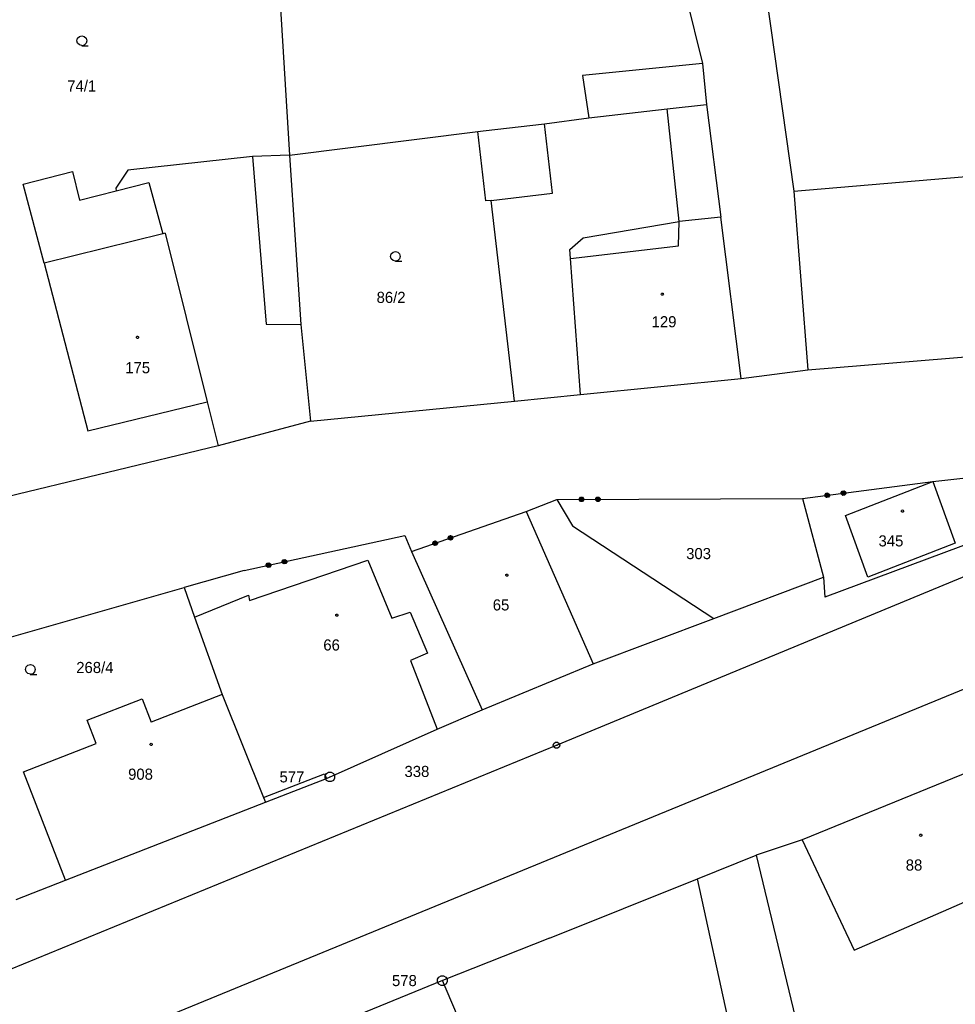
# Model space of a CAD drawing. Extents: x -757994 to -755874, y -1047691 to -1046119.
# Drawn here: x -757332.6 to -757261.1, y -1047147.5 to -1047072.3 of the extents above; entities that cross this region are included whole.
import ezdxf

# ---------------------------------------------------------------- set-up
doc = ezdxf.new("R2010")
doc.units = 0
doc.layers.add('katastrální mapa', color=7, linetype='Continuous')

msp = doc.modelspace()

# ---------------------------------------------------------------- linework, layer by layer
at = {"layer": 'katastrální mapa'}
for p, q in [((-757313.6, -1047056.48), (-757311.96, -1047082.63)), ((-757284.87, -1047057.51), (-757280.42, -1047075.65)), ((-757276.65, -1047062.56), (-757273.46, -1047085.38)), ((-757280.42, -1047075.65), (-757289.58, -1047076.55)), ((-757280.42, -1047075.65), (-757280.12, -1047078.76)), ((-757289.58, -1047076.55), (-757289.1, -1047079.79)), ((-757289.1, -1047079.79), (-757283.13, -1047079.1)), ((-757283.13, -1047079.1), (-757280.12, -1047078.76)), ((-757282.2, -1047087.71), (-757283.13, -1047079.1)), ((-757280.12, -1047078.76), (-757279.03, -1047087.37)), ((-757292.49, -1047080.24), (-757289.1, -1047079.79)), ((-757297.58, -1047080.84), (-757297.18, -1047080.79)), ((-757297.18, -1047080.79), (-757292.49, -1047080.24)), ((-757291.87, -1047085.55), (-757292.49, -1047080.24)), ((-757311.96, -1047082.63), (-757297.58, -1047080.84)), ((-757296.96, -1047086.14), (-757297.58, -1047080.84)), ((-757314.78, -1047082.75), (-757324.32, -1047083.79)), ((-757311.96, -1047082.63), (-757314.78, -1047082.75)), ((-757314.78, -1047082.75), (-757313.74, -1047095.54)), ((-757311.96, -1047082.63), (-757311.09, -1047095.57)), ((-757324.32, -1047083.79), (-757325.22, -1047085.16)), ((-757332.3, -1047084.86), (-757328.54, -1047083.9)), ((-757328.54, -1047083.9), (-757327.99, -1047086.07)), ((-757273.46, -1047085.38), (-757256.94, -1047083.99)), ((-757330.71, -1047090.88), (-757332.3, -1047084.86)), ((-757325.22, -1047085.16), (-757325.19, -1047085.37)), ((-757325.19, -1047085.37), (-757322.7, -1047084.74)), ((-757322.7, -1047084.74), (-757321.64, -1047088.65)), ((-757327.99, -1047086.07), (-757325.19, -1047085.37)), ((-757296.56, -1047086.1), (-757291.87, -1047085.55)), ((-757273.46, -1047085.38), (-757272.37, -1047099.04)), ((-757296.56, -1047086.1), (-757296.96, -1047086.14)), ((-757294.78, -1047101.42), (-757296.56, -1047086.1)), ((-757279.03, -1047087.37), (-757282.2, -1047087.71)), ((-757277.48, -1047099.7), (-757279.03, -1047087.37)), ((-757289.54, -1047088.95), (-757282.2, -1047087.71)), ((-757282.26, -1047089.56), (-757282.2, -1047087.71)), ((-757321.64, -1047088.65), (-757330.71, -1047090.88)), ((-757321.47, -1047088.61), (-757321.64, -1047088.65)), ((-757321.47, -1047088.61), (-757318.26, -1047101.48)), ((-757290.56, -1047089.84), (-757289.54, -1047088.95)), ((-757290.51, -1047090.53), (-757282.26, -1047089.56)), ((-757290.51, -1047090.53), (-757290.56, -1047089.84)), ((-757289.75, -1047100.92), (-757290.51, -1047090.53)), ((-757330.71, -1047090.88), (-757327.36, -1047103.7)), ((-757291.57, -1047127.72), (-757211.4, -1047094.51)), ((-757313.74, -1047095.54), (-757311.09, -1047095.57)), ((-757311.09, -1047095.57), (-757310.35, -1047102.96)), ((-757272.37, -1047099.04), (-757256.2, -1047097.7)), ((-757277.48, -1047099.7), (-757272.37, -1047099.04)), ((-757289.75, -1047100.92), (-757277.48, -1047099.7)), ((-757294.78, -1047101.42), (-757289.75, -1047100.92)), ((-757207.43, -1047101.65), (-757361.65, -1047164.98)), ((-757327.36, -1047103.7), (-757318.26, -1047101.48)), ((-757318.26, -1047101.48), (-757317.4, -1047104.85)), ((-757310.35, -1047102.96), (-757294.78, -1047101.42)), ((-757310.35, -1047102.96), (-757317.4, -1047104.85)), ((-757317.4, -1047104.85), (-757335.99, -1047109.34)), ((-757243.71, -1047106.19), (-757271.09, -1047116.4)), ((-757262.83, -1047107.57), (-757251.34, -1047106.28)), ((-757272.78, -1047108.86), (-757262.83, -1047107.57)), ((-757269.51, -1047110.17), (-757262.83, -1047107.57)), ((-757262.83, -1047107.57), (-757261.12, -1047112.27)), ((-757293.88, -1047109.85), (-757291.56, -1047108.94)), ((-757291.56, -1047108.94), (-757272.78, -1047108.86)), ((-757291.56, -1047108.94), (-757290.35, -1047110.95)), ((-757272.78, -1047108.86), (-757271.18, -1047114.87)), ((-757302.64, -1047112.91), (-757293.88, -1047109.85)), ((-757293.88, -1047109.85), (-757288.78, -1047121.5)), ((-757267.8, -1047114.87), (-757269.51, -1047110.17)), ((-757290.35, -1047110.95), (-757279.56, -1047118.03)), ((-757315.42, -1047114.36), (-757303.15, -1047111.7)), ((-757303.15, -1047111.7), (-757302.64, -1047112.91)), ((-757261.12, -1047112.27), (-757267.8, -1047114.87)), ((-757302.64, -1047112.91), (-757297.25, -1047125)), ((-757315.03, -1047116.67), (-757305.98, -1047113.59)), ((-757305.98, -1047113.59), (-757304.14, -1047118.02)), ((-757315.42, -1047114.36), (-757320.02, -1047115.67)), ((-757279.56, -1047118.03), (-757271.18, -1047114.87)), ((-757271.18, -1047114.87), (-757271.09, -1047116.4)), ((-757335.12, -1047119.99), (-757320.02, -1047115.67)), ((-757320.02, -1047115.67), (-757319.22, -1047117.92)), ((-757319.22, -1047117.92), (-757315.1, -1047116.25)), ((-757315.1, -1047116.25), (-757315.03, -1047116.67)), ((-757304.14, -1047118.02), (-757302.74, -1047117.56)), ((-757302.74, -1047117.56), (-757301.43, -1047120.67)), ((-757319.22, -1047117.92), (-757317.11, -1047123.83)), ((-757288.78, -1047121.5), (-757279.56, -1047118.03)), ((-757301.43, -1047120.67), (-757302.72, -1047121.25)), ((-757302.72, -1047121.25), (-757300.7, -1047126.49)), ((-757297.25, -1047125), (-757288.78, -1047121.5)), ((-757327.42, -1047125.81), (-757323.22, -1047124.17)), ((-757323.22, -1047124.17), (-757322.53, -1047125.95)), ((-757317.11, -1047123.83), (-757322.53, -1047125.95)), ((-757317.11, -1047123.83), (-757313.94, -1047131.7)), ((-757300.7, -1047126.49), (-757297.25, -1047125)), ((-757326.73, -1047127.59), (-757327.42, -1047125.81)), ((-757309.14, -1047130.25), (-757300.7, -1047126.49)), ((-757367, -1047158.64), (-757291.57, -1047127.72)), ((-757332.28, -1047129.75), (-757326.73, -1047127.59)), ((-757291.63, -1047127.72), (-757291.51, -1047127.72)), ((-757258.96, -1047129.28), (-757272.8, -1047134.93)), ((-757329.06, -1047138.02), (-757332.28, -1047129.75)), ((-757313.94, -1047131.7), (-757309.29, -1047129.91)), ((-757313.8, -1047132.07), (-757309.14, -1047130.25)), ((-757309.29, -1047129.91), (-757309.14, -1047130.25)), ((-757308.905, -1047130.13), (-757308.855, -1047130.13)), ((-757313.94, -1047131.7), (-757313.8, -1047132.07)), ((-757329.06, -1047138.02), (-757313.8, -1047132.07)), ((-757272.8, -1047134.93), (-757276.32, -1047136.12)), ((-757272.8, -1047134.93), (-757268.85, -1047143.38)), ((-757280.81, -1047137.92), (-757276.32, -1047136.12)), ((-757276.32, -1047136.12), (-757272.71, -1047151.06)), ((-757292.12, -1047142.46), (-757280.81, -1047137.92)), ((-757276.45, -1047157.77), (-757280.81, -1047137.92)), ((-757268.85, -1047143.38), (-757255.53, -1047137.56)), ((-757332.84, -1047139.49), (-757329.06, -1047138.02)), ((-757292.12, -1047142.46), (-757300.29, -1047145.69)), ((-757300.29, -1047145.69), (-757308.3, -1047148.96)), ((-757300.315, -1047145.69), (-757300.265, -1047145.69)), ((-757296.33, -1047154.93), (-757300.29, -1047145.69))]:
    msp.add_line(p, q, dxfattribs=at)
for points in [[(-757327.82, -1047074.27), (-757328.01, -1047074.22), (-757328.145, -1047074.085), (-757328.195, -1047073.9), (-757328.145, -1047073.715), (-757328.01, -1047073.58), (-757327.825, -1047073.53), (-757327.64, -1047073.58), (-757327.505, -1047073.715), (-757327.455, -1047073.905), (-757327.505, -1047074.095), (-757327.64, -1047074.23), (-757327.83, -1047074.28), (-757327.33, -1047074.28)], [(-757303.87, -1047090.74), (-757304.06, -1047090.69), (-757304.195, -1047090.555), (-757304.245, -1047090.37), (-757304.195, -1047090.185), (-757304.06, -1047090.05), (-757303.875, -1047090), (-757303.69, -1047090.05), (-757303.555, -1047090.185), (-757303.505, -1047090.375), (-757303.555, -1047090.565), (-757303.69, -1047090.7), (-757303.88, -1047090.75), (-757303.38, -1047090.75)], [(-757270.852, -1047108.449), (-757270.745, -1047108.531), (-757270.728, -1047108.665), (-757270.81, -1047108.771), (-757270.944, -1047108.788), (-757271.05, -1047108.706), (-757271.068, -1047108.573), (-757270.986, -1047108.466), (-757270.852, -1047108.449), (-757270.854, -1047108.469), (-757270.973, -1047108.485), (-757271.008, -1047108.529), (-757270.809, -1047108.504), (-757270.765, -1047108.538), (-757271.042, -1047108.574), (-757271.037, -1047108.614), (-757270.76, -1047108.578), (-757270.754, -1047108.618), (-757271.032, -1047108.654), (-757271.027, -1047108.693), (-757270.749, -1047108.657), (-757270.784, -1047108.702), (-757270.982, -1047108.728), (-757270.937, -1047108.762), (-757270.818, -1047108.747)], [(-757269.612, -1047108.288), (-757269.506, -1047108.37), (-757269.488, -1047108.504), (-757269.57, -1047108.61), (-757269.704, -1047108.628), (-757269.811, -1047108.546), (-757269.828, -1047108.412), (-757269.746, -1047108.305), (-757269.612, -1047108.288), (-757269.625, -1047108.31), (-757269.744, -1047108.325), (-757269.778, -1047108.37), (-757269.58, -1047108.344), (-757269.535, -1047108.379), (-757269.813, -1047108.415), (-757269.807, -1047108.454), (-757269.53, -1047108.418), (-757269.525, -1047108.458), (-757269.802, -1047108.494), (-757269.797, -1047108.534), (-757269.52, -1047108.498), (-757269.554, -1047108.543), (-757269.752, -1047108.568), (-757269.708, -1047108.603), (-757269.589, -1047108.587)], [(-757289.596, -1047108.771), (-757289.5, -1047108.866), (-757289.5, -1047109.001), (-757289.594, -1047109.096), (-757289.729, -1047109.097), (-757289.825, -1047109.002), (-757289.825, -1047108.867), (-757289.731, -1047108.772), (-757289.596, -1047108.771), (-757289.601, -1047108.792), (-757289.721, -1047108.792), (-757289.76, -1047108.832), (-757289.56, -1047108.831), (-757289.52, -1047108.871), (-757289.8, -1047108.872), (-757289.8, -1047108.912), (-757289.52, -1047108.911), (-757289.52, -1047108.951), (-757289.8, -1047108.952), (-757289.8, -1047108.992), (-757289.52, -1047108.991), (-757289.56, -1047109.031), (-757289.76, -1047109.032), (-757289.719, -1047109.072), (-757289.599, -1047109.072)], [(-757288.346, -1047108.766), (-757288.25, -1047108.861), (-757288.25, -1047108.996), (-757288.344, -1047109.091), (-757288.479, -1047109.092), (-757288.575, -1047108.997), (-757288.575, -1047108.862), (-757288.481, -1047108.767), (-757288.346, -1047108.766), (-757288.361, -1047108.787), (-757288.481, -1047108.787), (-757288.52, -1047108.827), (-757288.32, -1047108.826), (-757288.28, -1047108.866), (-757288.56, -1047108.867), (-757288.56, -1047108.907), (-757288.28, -1047108.906), (-757288.28, -1047108.946), (-757288.56, -1047108.947), (-757288.56, -1047108.987), (-757288.28, -1047108.986), (-757288.32, -1047109.026), (-757288.52, -1047109.027), (-757288.479, -1047109.067), (-757288.359, -1047109.067)], [(-757300.838, -1047112.111), (-757300.717, -1047112.169), (-757300.672, -1047112.297), (-757300.731, -1047112.418), (-757300.858, -1047112.462), (-757300.979, -1047112.404), (-757301.024, -1047112.276), (-757300.965, -1047112.155), (-757300.838, -1047112.111), (-757300.836, -1047112.131), (-757300.949, -1047112.171), (-757300.974, -1047112.222), (-757300.785, -1047112.156), (-757300.734, -1047112.181), (-757300.998, -1047112.273), (-757300.985, -1047112.311), (-757300.721, -1047112.218), (-757300.708, -1047112.256), (-757300.972, -1047112.348), (-757300.959, -1047112.386), (-757300.694, -1047112.294), (-757300.719, -1047112.345), (-757300.908, -1047112.411), (-757300.857, -1047112.435), (-757300.743, -1047112.396)], [(-757299.658, -1047111.699), (-757299.537, -1047111.757), (-757299.492, -1047111.885), (-757299.55, -1047112.006), (-757299.678, -1047112.05), (-757299.799, -1047111.992), (-757299.843, -1047111.864), (-757299.785, -1047111.743), (-757299.658, -1047111.699), (-757299.665, -1047111.723), (-757299.778, -1047111.762), (-757299.803, -1047111.813), (-757299.614, -1047111.747), (-757299.563, -1047111.772), (-757299.828, -1047111.864), (-757299.814, -1047111.902), (-757299.55, -1047111.81), (-757299.537, -1047111.847), (-757299.801, -1047111.94), (-757299.788, -1047111.977), (-757299.524, -1047111.885), (-757299.548, -1047111.936), (-757299.737, -1047112.002), (-757299.686, -1047112.027), (-757299.573, -1047111.987)], [(-757313.533, -1047113.787), (-757313.421, -1047113.86), (-757313.392, -1047113.992), (-757313.465, -1047114.105), (-757313.597, -1047114.133), (-757313.71, -1047114.06), (-757313.738, -1047113.929), (-757313.665, -1047113.816), (-757313.533, -1047113.787), (-757313.534, -1047113.808), (-757313.651, -1047113.833), (-757313.682, -1047113.881), (-757313.487, -1047113.838), (-757313.439, -1047113.869), (-757313.713, -1047113.928), (-757313.704, -1047113.967), (-757313.431, -1047113.908), (-757313.422, -1047113.947), (-757313.696, -1047114.006), (-757313.687, -1047114.045), (-757313.414, -1047113.986), (-757313.444, -1047114.034), (-757313.64, -1047114.076), (-757313.592, -1047114.107), (-757313.475, -1047114.081)], [(-757312.312, -1047113.523), (-757312.199, -1047113.596), (-757312.17, -1047113.728), (-757312.243, -1047113.84), (-757312.375, -1047113.869), (-757312.488, -1047113.796), (-757312.516, -1047113.664), (-757312.444, -1047113.551), (-757312.312, -1047113.523), (-757312.322, -1047113.546), (-757312.439, -1047113.571), (-757312.47, -1047113.618), (-757312.275, -1047113.576), (-757312.227, -1047113.607), (-757312.501, -1047113.666), (-757312.492, -1047113.705), (-757312.219, -1047113.646), (-757312.21, -1047113.685), (-757312.484, -1047113.744), (-757312.475, -1047113.783), (-757312.202, -1047113.724), (-757312.232, -1047113.772), (-757312.428, -1047113.814), (-757312.38, -1047113.845), (-757312.263, -1047113.819)], [(-757331.75, -1047122.29), (-757331.94, -1047122.24), (-757332.075, -1047122.105), (-757332.125, -1047121.92), (-757332.075, -1047121.735), (-757331.94, -1047121.6), (-757331.755, -1047121.55), (-757331.57, -1047121.6), (-757331.435, -1047121.735), (-757331.385, -1047121.925), (-757331.435, -1047122.115), (-757331.57, -1047122.25), (-757331.76, -1047122.3), (-757331.26, -1047122.3)]]:
    msp.add_lwpolyline(points, dxfattribs=at)
for points in [[(-757283.49, -1047093.175), (-757283.44, -1047093.185), (-757283.415, -1047093.23), (-757283.405, -1047093.26), (-757283.415, -1047093.305), (-757283.455, -1047093.34), (-757283.49, -1047093.345), (-757283.535, -1047093.33), (-757283.565, -1047093.3), (-757283.575, -1047093.26), (-757283.565, -1047093.215), (-757283.525, -1047093.18)], [(-757323.57, -1047096.475), (-757323.52, -1047096.485), (-757323.495, -1047096.53), (-757323.485, -1047096.56), (-757323.495, -1047096.605), (-757323.535, -1047096.64), (-757323.57, -1047096.645), (-757323.615, -1047096.63), (-757323.645, -1047096.6), (-757323.655, -1047096.56), (-757323.645, -1047096.515), (-757323.605, -1047096.48)], [(-757265.16, -1047109.745), (-757265.11, -1047109.755), (-757265.085, -1047109.8), (-757265.075, -1047109.83), (-757265.085, -1047109.875), (-757265.125, -1047109.91), (-757265.16, -1047109.915), (-757265.205, -1047109.9), (-757265.235, -1047109.87), (-757265.245, -1047109.83), (-757265.235, -1047109.785), (-757265.195, -1047109.75)], [(-757295.36, -1047114.635), (-757295.31, -1047114.645), (-757295.285, -1047114.69), (-757295.275, -1047114.72), (-757295.285, -1047114.765), (-757295.325, -1047114.8), (-757295.36, -1047114.805), (-757295.405, -1047114.79), (-757295.435, -1047114.76), (-757295.445, -1047114.72), (-757295.435, -1047114.675), (-757295.395, -1047114.64)], [(-757308.34, -1047117.695), (-757308.29, -1047117.705), (-757308.265, -1047117.75), (-757308.255, -1047117.78), (-757308.265, -1047117.825), (-757308.305, -1047117.86), (-757308.34, -1047117.865), (-757308.385, -1047117.85), (-757308.415, -1047117.82), (-757308.425, -1047117.78), (-757308.415, -1047117.735), (-757308.375, -1047117.7)], [(-757322.54, -1047127.565), (-757322.49, -1047127.575), (-757322.465, -1047127.62), (-757322.455, -1047127.65), (-757322.465, -1047127.695), (-757322.505, -1047127.73), (-757322.54, -1047127.735), (-757322.585, -1047127.72), (-757322.615, -1047127.69), (-757322.625, -1047127.65), (-757322.615, -1047127.605), (-757322.575, -1047127.57)], [(-757291.495, -1047127.48), (-757291.37, -1047127.57), (-757291.32, -1047127.715), (-757291.37, -1047127.86), (-757291.495, -1047127.95), (-757291.65, -1047127.95), (-757291.775, -1047127.86), (-757291.825, -1047127.715), (-757291.775, -1047127.57), (-757291.65, -1047127.48)], [(-757308.785, -1047129.77), (-757308.615, -1047129.865), (-757308.52, -1047130.035), (-757308.52, -1047130.23), (-757308.615, -1047130.4), (-757308.785, -1047130.495), (-757308.98, -1047130.495), (-757309.15, -1047130.4), (-757309.245, -1047130.23), (-757309.245, -1047130.035), (-757309.15, -1047129.865), (-757308.98, -1047129.77)], [(-757263.76, -1047134.505), (-757263.71, -1047134.515), (-757263.685, -1047134.56), (-757263.675, -1047134.59), (-757263.685, -1047134.635), (-757263.725, -1047134.67), (-757263.76, -1047134.675), (-757263.805, -1047134.66), (-757263.835, -1047134.63), (-757263.845, -1047134.59), (-757263.835, -1047134.545), (-757263.795, -1047134.51)], [(-757300.195, -1047145.33), (-757300.025, -1047145.425), (-757299.93, -1047145.595), (-757299.93, -1047145.79), (-757300.025, -1047145.96), (-757300.195, -1047146.055), (-757300.39, -1047146.055), (-757300.56, -1047145.96), (-757300.655, -1047145.79), (-757300.655, -1047145.595), (-757300.56, -1047145.425), (-757300.39, -1047145.33)]]:
    msp.add_lwpolyline(points, close=True, dxfattribs=at)

# ---------------------------------------------------------------- texts
for s, p in [('74/1', (-757328.938, -1047077.78)), ('86/2', (-757305.312, -1047093.93)), ('129', (-757284.31, -1047095.79)), ('175', (-757324.506, -1047099.3)), ('345', (-757266.981, -1047112.53)), ('303', (-757281.671, -1047113.5)), ('65', (-757296.442, -1047117.42)), ('66', (-757309.382, -1047120.48)), ('268/4', (-757328.251, -1047122.2)), ('908', (-757324.291, -1047130.35)), ('338', (-757303.181, -1047130.14)), ('577', (-757312.727, -1047130.555)), ('88', (-757264.901, -1047137.29)), ('578', (-757304.137, -1047146.115))]:
    msp.add_text(s, height=0.85, dxfattribs=at).set_placement(p)

doc.saveas('drawing.dxf')
